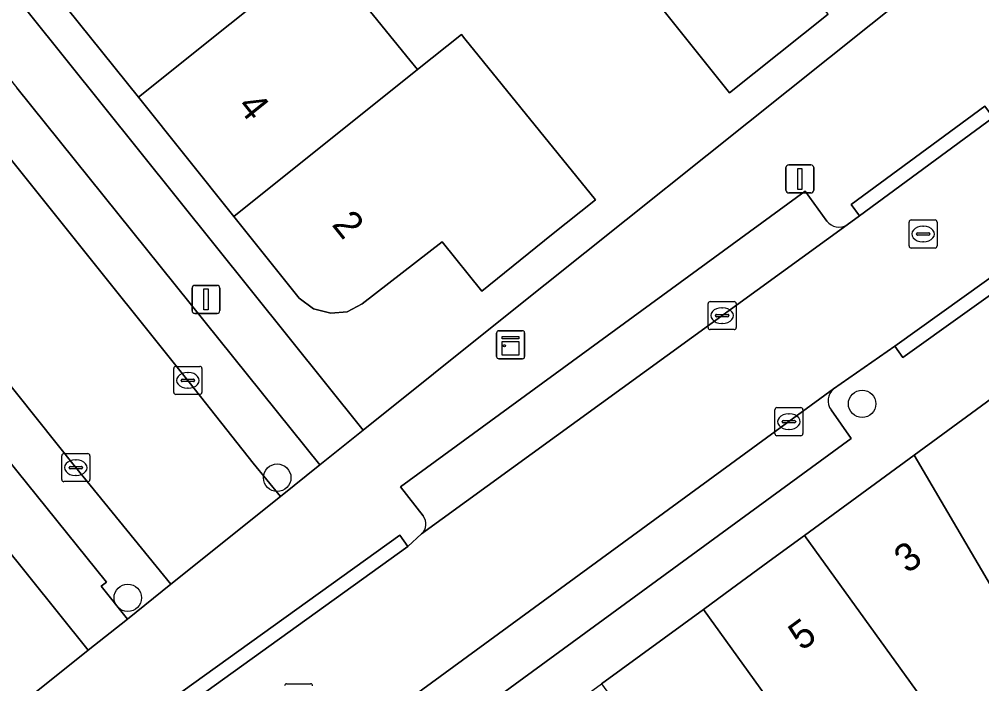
# Model space of a CAD drawing. Extents: x 161771 to 163125, y 382475 to 383179.
# Drawn here: x 162131 to 162165.3, y 382895.24 to 382918.93 of the extents above; entities that cross this region are included whole.
import ezdxf

# ---------------------------------------------------------------- set-up
doc = ezdxf.new("R2010")
doc.units = 0
for name, color, linetype in [('IMGEO_Boom', 7, 'Continuous'), ('IMGEO_Erf', 7, 'Continuous'), ('IMGEO_Kast', 7, 'Continuous'), ('IMGEO_Kolk', 7, 'Continuous'), ('IMGEO_Lichtmast', 7, 'Continuous'), ('IMGEO_Pand', 7, 'Continuous'), ('IMGEO_Pand_nummerreeks', 7, 'Continuous'), ('IMGEO_Parkeervlak_open', 7, 'Continuous'), ('IMGEO_Rijbaan_lokaal_open', 7, 'Continuous'), ('IMGEO_Rioolput', 7, 'Continuous'), ('IMGEO_Voetpad_open', 7, 'Continuous'), ('IMGEO_Woonerf_open', 7, 'Continuous')]:
    doc.layers.add(name, color=color, linetype=linetype)

msp = doc.modelspace()

# ---------------------------------------------------------------- linework, layer by layer
at = {"layer": 'IMGEO_Boom'}
for centre in [(162161.037, 382905.221), (162140.194, 382902.589), (162134.866, 382898.309)]:
    msp.add_circle(centre, 0.489, dxfattribs=at)
at = {"layer": 'IMGEO_Erf'}
for points in [[(162119.361, 382885.166), (162133.454, 382896.443), (162070.869, 382974.514)], [(162096.877, 382962.151), (162143.255, 382904.278), (162148.274, 382908.294), (162171.48, 382926.845)], [(162159.833, 382919.109), (162156.311, 382916.302), (162151.576, 382922.244)], [(162141.765, 382921.364), (162144.924, 382917.47), (162145.193, 382917.138), (162146.755, 382918.388), (162146.88, 382918.233), (162151.533, 382912.494), (162149.969, 382911.248), (162147.491, 382909.238), (162146.068, 382910.992), (162143.222, 382908.782), (162142.685, 382908.505), (162142.11, 382908.456), (162141.488, 382908.607), (162140.975, 382908.991), (162138.647, 382911.901), (162135.247, 382916.15), (162131.831, 382920.419)]]:
    msp.add_lwpolyline(points, dxfattribs=at)
at = {"layer": 'IMGEO_Kast'}
for p, q in [((162148.01, 382906.904), (162148.01, 382907.745)), ((162148.01, 382907.745), (162148.01, 382906.904)), ((162148.085, 382907.829), (162148.926, 382907.829)), ((162148.926, 382907.829), (162148.085, 382907.829)), ((162149.01, 382907.754), (162149.01, 382906.913)), ((162149.01, 382906.913), (162149.01, 382907.754)), ((162148.935, 382906.829), (162148.094, 382906.829)), ((162148.094, 382906.829), (162148.935, 382906.829))]:
    msp.add_line(p, q, dxfattribs=at)
for points in [[(162148.205, 382907.619), (162148.805, 382907.619), (162148.805, 382907.534), (162148.205, 382907.534), (162148.205, 382907.619)], [(162148.205, 382907.444), (162148.805, 382907.444), (162148.805, 382906.955), (162148.205, 382906.955), (162148.205, 382907.444)]]:
    msp.add_lwpolyline(points, dxfattribs=at)
msp.add_circle((162148.289, 382907.293), 0.0377, dxfattribs=at)
for centre, start, end in [((162148.088, 382907.751), 92.4484, 184.2845), ((162148.088, 382907.751), 92.4484, 184.2845), ((162148.932, 382907.751), 2.4484, 94.2845), ((162148.932, 382907.751), 2.4484, 94.2845), ((162148.088, 382906.907), 182.4484, 274.2845), ((162148.088, 382906.907), 182.4484, 274.2845), ((162148.932, 382906.907), 272.4484, 4.2845), ((162148.932, 382906.907), 272.4484, 4.2845)]:
    msp.add_arc(centre, 0.0779, start, end, dxfattribs=at)
at = {"layer": 'IMGEO_Kolk'}
for p, q in [((162155.549, 382907.941), (162155.549, 382908.793)), ((162155.624, 382908.867), (162156.476, 382908.867)), ((162156.037, 382908.647), (162156.062, 382908.647)), ((162156.55, 382908.793), (162156.55, 382907.941)), ((162155.808, 382908.361), (162155.808, 382908.373)), ((162156.246, 382908.324), (162155.848, 382908.324)), ((162155.851, 382908.41), (162156.249, 382908.41)), ((162156.292, 382908.373), (162156.292, 382908.361)), ((162156.06, 382908.087), (162156.035, 382908.087)), ((162156.476, 382907.867), (162155.624, 382907.867)), ((162136.583, 382906.557), (162137.435, 382906.557)), ((162136.508, 382905.631), (162136.508, 382906.483)), ((162136.996, 382906.337), (162137.021, 382906.337)), ((162137.509, 382906.483), (162137.509, 382905.631)), ((162136.767, 382906.051), (162136.767, 382906.063)), ((162137.205, 382906.014), (162136.807, 382906.014)), ((162136.81, 382906.1), (162137.208, 382906.1)), ((162137.251, 382906.063), (162137.251, 382906.051)), ((162137.435, 382905.557), (162136.583, 382905.557)), ((162137.019, 382905.777), (162136.994, 382905.777)), ((162157.927, 382904.16), (162157.927, 382905.012)), ((162158.002, 382905.086), (162158.854, 382905.086)), ((162158.415, 382904.866), (162158.44, 382904.866)), ((162158.928, 382905.012), (162158.928, 382904.16)), ((162158.186, 382904.58), (162158.186, 382904.592)), ((162158.624, 382904.543), (162158.226, 382904.543)), ((162158.229, 382904.629), (162158.627, 382904.629)), ((162158.67, 382904.592), (162158.67, 382904.58)), ((162158.438, 382904.306), (162158.413, 382904.306)), ((162158.854, 382904.086), (162158.002, 382904.086)), ((162132.591, 382903.448), (162133.443, 382903.448)), ((162132.516, 382902.522), (162132.516, 382903.374)), ((162133.004, 382903.228), (162133.029, 382903.228)), ((162133.517, 382903.374), (162133.517, 382902.522)), ((162132.775, 382902.942), (162132.775, 382902.954)), ((162133.213, 382902.905), (162132.815, 382902.905)), ((162132.818, 382902.991), (162133.216, 382902.991)), ((162133.259, 382902.954), (162133.259, 382902.942)), ((162133.443, 382902.448), (162132.591, 382902.448)), ((162133.027, 382902.668), (162133.002, 382902.668))]:
    msp.add_line(p, q, dxfattribs=at)
for points in [[(162155.549, 382907.941), (162155.549, 382908.793)], [(162155.624, 382908.867), (162156.476, 382908.867)], [(162156.55, 382908.793), (162156.55, 382907.941)], [(162156.476, 382907.867), (162155.624, 382907.867)], [(162136.583, 382906.557), (162137.435, 382906.557)], [(162136.508, 382905.631), (162136.508, 382906.483)], [(162137.509, 382906.483), (162137.509, 382905.631)], [(162137.435, 382905.557), (162136.583, 382905.557)], [(162157.927, 382904.16), (162157.927, 382905.012)], [(162158.002, 382905.086), (162158.854, 382905.086)], [(162158.928, 382905.012), (162158.928, 382904.16)], [(162158.854, 382904.086), (162158.002, 382904.086)], [(162132.591, 382903.448), (162133.443, 382903.448)], [(162132.516, 382902.522), (162132.516, 382903.374)], [(162133.517, 382903.374), (162133.517, 382902.522)], [(162133.443, 382902.448), (162132.591, 382902.448)]]:
    msp.add_lwpolyline(points, dxfattribs=at)
for centre, radius, start, end in [((162155.626, 382908.791), 0.0765, 91.552, 178.448), ((162155.626, 382908.791), 0.0765, 91.552, 178.448), ((162156.474, 382908.791), 0.0765, 1.552, 88.448), ((162156.474, 382908.791), 0.0765, 1.552, 88.448), ((162155.848, 382908.37), 0.0403, 85.8775, 175.7526), ((162155.845, 382908.36), 0.0366, 178.938, 274.7102), ((162156.249, 382908.367), 0.043, 264.8664, 352.4533), ((162156.253, 382908.372), 0.0386, 1.7309, 96.639), ((162155.626, 382907.943), 0.0765, 181.552, 268.448), ((162155.626, 382907.943), 0.0765, 181.552, 268.448), ((162156.474, 382907.943), 0.0765, 271.552, 358.448), ((162156.474, 382907.943), 0.0765, 271.552, 358.448), ((162136.585, 382906.481), 0.0765, 91.552, 178.448), ((162136.585, 382906.481), 0.0765, 91.552, 178.448), ((162137.433, 382906.481), 0.0765, 1.552, 88.448), ((162137.433, 382906.481), 0.0765, 1.552, 88.448), ((162136.807, 382906.06), 0.0403, 85.8775, 175.7526), ((162136.804, 382906.05), 0.0366, 178.938, 274.7102), ((162137.208, 382906.057), 0.043, 264.8664, 352.4533), ((162137.212, 382906.062), 0.0386, 1.7309, 96.639), ((162136.585, 382905.633), 0.0765, 181.552, 268.448), ((162136.585, 382905.633), 0.0765, 181.552, 268.448), ((162137.433, 382905.633), 0.0765, 271.552, 358.448), ((162137.433, 382905.633), 0.0765, 271.552, 358.448), ((162158.004, 382905.01), 0.0765, 91.552, 178.448), ((162158.004, 382905.01), 0.0765, 91.552, 178.448), ((162158.852, 382905.01), 0.0765, 1.552, 88.448), ((162158.852, 382905.01), 0.0765, 1.552, 88.448), ((162158.226, 382904.589), 0.0403, 85.8775, 175.7526), ((162158.223, 382904.579), 0.0366, 178.938, 274.7102), ((162158.627, 382904.586), 0.043, 264.8664, 352.4533), ((162158.631, 382904.591), 0.0386, 1.7309, 96.639), ((162158.004, 382904.162), 0.0765, 181.552, 268.448), ((162158.004, 382904.162), 0.0765, 181.552, 268.448), ((162158.852, 382904.162), 0.0765, 271.552, 358.448), ((162158.852, 382904.162), 0.0765, 271.552, 358.448), ((162132.593, 382903.372), 0.0765, 91.552, 178.448), ((162132.593, 382903.372), 0.0765, 91.552, 178.448), ((162133.441, 382903.372), 0.0765, 1.552, 88.448), ((162133.441, 382903.372), 0.0765, 1.552, 88.448), ((162132.815, 382902.951), 0.0403, 85.8775, 175.7526), ((162132.812, 382902.941), 0.0366, 178.938, 274.7102), ((162133.216, 382902.948), 0.043, 264.8664, 352.4533), ((162133.22, 382902.953), 0.0386, 1.7309, 96.639), ((162132.593, 382902.524), 0.0765, 181.552, 268.448), ((162132.593, 382902.524), 0.0765, 181.552, 268.448), ((162133.441, 382902.524), 0.0765, 271.552, 358.448), ((162133.441, 382902.524), 0.0765, 271.552, 358.448)]:
    msp.add_arc(centre, radius, start, end, dxfattribs=at)
for centre, major_axis, ratio, start_param, end_param in [((162156.036, 382908.367), (-0.387, 0.002), 0.722429, 4.712389, 7.853982), ((162156.061, 382908.367), (-0.39, 0.002), 0.717154, 1.570796, 4.712389), ((162136.995, 382906.057), (-0.387, 0.002), 0.722429, 4.712389, 7.853982), ((162137.02, 382906.057), (-0.39, 0.002), 0.717154, 1.570796, 4.712389), ((162158.414, 382904.586), (-0.387, 0.002), 0.722429, 4.712389, 7.853982), ((162158.439, 382904.586), (-0.39, 0.002), 0.717154, 1.570796, 4.712389), ((162133.003, 382902.948), (-0.387, 0.002), 0.722429, 4.712389, 7.853982), ((162133.028, 382902.948), (-0.39, 0.002), 0.717154, 1.570796, 4.712389)]:
    msp.add_ellipse(centre, major_axis=major_axis, ratio=ratio, start_param=start_param, end_param=end_param, dxfattribs=at)
at = {"layer": 'IMGEO_Lichtmast'}
for p, q in [((162158.424, 382913.74), (162159.214, 382913.74)), ((162159.214, 382913.74), (162158.424, 382913.74)), ((162158.324, 382912.84), (162158.324, 382913.64)), ((162158.324, 382913.64), (162158.324, 382912.84)), ((162159.314, 382913.64), (162159.314, 382912.84)), ((162159.314, 382912.84), (162159.314, 382913.64)), ((162159.214, 382912.74), (162158.424, 382912.74)), ((162158.424, 382912.74), (162159.214, 382912.74)), ((162137.16, 382908.543), (162137.16, 382909.343)), ((162137.16, 382909.343), (162137.16, 382908.543)), ((162137.26, 382909.443), (162138.05, 382909.443)), ((162138.05, 382909.443), (162137.26, 382909.443)), ((162138.15, 382909.343), (162138.15, 382908.543)), ((162138.15, 382908.543), (162138.15, 382909.343)), ((162138.05, 382908.443), (162137.26, 382908.443)), ((162137.26, 382908.443), (162138.05, 382908.443))]:
    msp.add_line(p, q, dxfattribs=at)
for points in [[(162158.744, 382913.615), (162158.894, 382913.615), (162158.894, 382912.865), (162158.744, 382912.865), (162158.744, 382913.615)], [(162137.58, 382909.318), (162137.73, 382909.318), (162137.73, 382908.568), (162137.58, 382908.568), (162137.58, 382909.318)]]:
    msp.add_lwpolyline(points, dxfattribs=at)
for centre, start, end in [((162158.424, 382913.64), 90, 180), ((162158.424, 382913.64), 90, 180), ((162159.214, 382913.64), 0, 90), ((162159.214, 382913.64), 360, 90), ((162158.424, 382912.84), 180, 270), ((162158.424, 382912.84), 180, 270), ((162159.214, 382912.84), 270, 0), ((162159.214, 382912.84), 270, 0), ((162137.26, 382909.343), 90, 180), ((162137.26, 382909.343), 90, 180), ((162138.05, 382909.343), 0, 90), ((162138.05, 382909.343), 360, 90), ((162137.26, 382908.543), 180, 270), ((162137.26, 382908.543), 180, 270), ((162138.05, 382908.543), 270, 0), ((162138.05, 382908.543), 270, 0)]:
    msp.add_arc(centre, 0.1, start, end, dxfattribs=at)
at = {"layer": 'IMGEO_Pand'}
for points in [[(162131.831, 382920.419), (162135.247, 382916.15), (162141.765, 382921.364), (162144.342, 382923.425), (162142.792, 382925.336), (162140.23, 382923.256), (162138.32, 382925.611)], [(162155.07, 382925.04), (162152.267, 382922.797), (162151.576, 382922.244), (162156.311, 382916.302), (162159.833, 382919.109)], [(162145.193, 382917.138), (162144.924, 382917.47), (162141.765, 382921.364), (162135.247, 382916.15), (162138.647, 382911.901)], [(162151.533, 382912.494), (162146.88, 382918.233), (162146.755, 382918.388), (162145.193, 382917.138), (162138.647, 382911.901), (162140.975, 382908.991), (162141.488, 382908.607), (162142.11, 382908.456), (162142.685, 382908.505), (162143.222, 382908.782), (162146.068, 382910.992), (162147.491, 382909.238), (162149.969, 382911.248)], [(162162.894, 382903.388), (162158.981, 382900.527), (162166.903, 382889.54), (162168.819, 382890.922), (162168.751, 382891.017), (162165.619, 382895.402), (162166.964, 382896.454), (162165.055, 382899.707)], [(162158.981, 382900.527), (162157.86, 382899.707), (162156.384, 382898.628), (162155.381, 382897.894), (162160.22, 382891.181), (162162.032, 382892.502), (162165.124, 382888.257), (162166.903, 382889.54)], [(162155.381, 382897.894), (162151.754, 382895.242), (162159.699, 382884.336), (162161.333, 382885.487), (162162.558, 382886.35), (162160.945, 382888.641), (162159.719, 382887.778), (162158.305, 382889.786), (162160.22, 382891.181)]]:
    msp.add_lwpolyline(points, close=True, dxfattribs=at)
at = {"layer": 'IMGEO_Parkeervlak_open'}
for points in [[(162093.61, 382961.455), (162093.815, 382962.38), (162093.77, 382962.818), (162093.596, 382963.187), (162079.124, 382981.195), (162077.729, 382980.054), (162078.737, 382978.916), (162082.043, 382974.428), (162092.505, 382961.71), (162095.538, 382957.905), (162096.482, 382956.694), (162109.857, 382939.975), (162119.562, 382927.825), (162122.601, 382924.093), (162122.694, 382923.973), (162123.703, 382922.674), (162137.054, 382905.998), (162139.34, 382903.102), (162140.307, 382901.917), (162141.717, 382903.048), (162130.917, 382916.483)], [(162124.165, 382911.199), (162134.109, 382898.871), (162133.924, 382898.728), (162134.86, 382897.546), (162136.406, 382898.79), (162133.002, 382902.97), (162119.914, 382919.373), (162118.699, 382920.849), (162115.63, 382924.69), (162105.843, 382937.034), (162092.723, 382953.402), (162091.583, 382954.731), (162088.546, 382958.539), (162073.842, 382976.876), (162072.439, 382975.73), (162086.885, 382957.787)], [(162159.785, 382911.734), (162159.007, 382912.797), (162144.588, 382902.261), (162145.397, 382901.226)], [(162145.341, 382900.591), (162160.501, 382911.597)], [(162160.018, 382905.751), (162137.732, 382889.454), (162135.365, 382887.723), (162125.393, 382880.431)], [(162126.151, 382880.323), (162126.857, 382879.291), (162140.141, 382888.996), (162160.652, 382903.982), (162159.93, 382905.004)]]:
    msp.add_lwpolyline(points, dxfattribs=at)
for centre, radius, start, end in [((162160.218, 382912.059), 0.542, 216.8935, 301.4423), ((162160.382, 382905.329), 0.557, 130.8339, 215.7286), ((162145.032, 382900.938), 0.465, 311.6582, 38.2622)]:
    msp.add_arc(centre, radius, start, end, dxfattribs=at)
at = {"layer": 'IMGEO_Rijbaan_lokaal_open'}
for points in [[(162136.672, 382894.252), (162135.907, 382893.712), (162135.462, 382893.398), (162135.086, 382893.123), (162137.732, 382889.454), (162160.018, 382905.751), (162162.202, 382907.274), (162168.658, 382911.904), (162169.91, 382912.836), (162202.304, 382936.515), (162199.544, 382940.182), (162198.547, 382939.458), (162197.661, 382938.791), (162196.496, 382937.909), (162189.901, 382933.103), (162188.634, 382932.194), (162166.246, 382915.883), (162165.705, 382915.432), (162160.94, 382911.921), (162160.501, 382911.597), (162145.341, 382900.591), (162144.852, 382900.14)], [(162122.694, 382923.973), (162118.699, 382920.849), (162119.914, 382919.373), (162133.002, 382902.97), (162136.406, 382898.79), (162140.307, 382901.917), (162139.34, 382903.102), (162137.054, 382905.998), (162123.703, 382922.674)]]:
    msp.add_lwpolyline(points, close=True, dxfattribs=at)
at = {"layer": 'IMGEO_Rioolput'}
for p, q in [((162162.711, 382910.85), (162162.711, 382911.702)), ((162162.786, 382911.776), (162163.638, 382911.776)), ((162163.712, 382911.702), (162163.712, 382910.85)), ((162163.013, 382911.319), (162163.411, 382911.319)), ((162163.199, 382911.556), (162163.224, 382911.556)), ((162162.97, 382911.27), (162162.97, 382911.282)), ((162163.408, 382911.233), (162163.01, 382911.233)), ((162163.222, 382910.996), (162163.197, 382910.996)), ((162163.454, 382911.282), (162163.454, 382911.27)), ((162163.638, 382910.776), (162162.786, 382910.776)), ((162140.53, 382895.244), (162141.382, 382895.244))]:
    msp.add_line(p, q, dxfattribs=at)
for points in [[(162162.711, 382910.85), (162162.711, 382911.702)], [(162162.786, 382911.776), (162163.638, 382911.776)], [(162163.712, 382911.702), (162163.712, 382910.85)], [(162163.638, 382910.776), (162162.786, 382910.776)], [(162140.53, 382895.244), (162141.382, 382895.244)]]:
    msp.add_lwpolyline(points, dxfattribs=at)
for centre, radius, start, end in [((162162.788, 382911.7), 0.0765, 91.552, 178.448), ((162162.788, 382911.7), 0.0765, 91.552, 178.448), ((162163.636, 382911.7), 0.0765, 1.552, 88.448), ((162163.636, 382911.7), 0.0765, 1.552, 88.448), ((162163.01, 382911.279), 0.0403, 85.8775, 175.7526), ((162163.415, 382911.281), 0.0386, 1.7309, 96.639), ((162163.007, 382911.269), 0.0366, 178.938, 274.7102), ((162163.411, 382911.276), 0.043, 264.8664, 352.4533), ((162162.788, 382910.852), 0.0765, 181.552, 268.448), ((162162.788, 382910.852), 0.0765, 181.552, 268.448), ((162163.636, 382910.852), 0.0765, 271.552, 358.448), ((162163.636, 382910.852), 0.0765, 271.552, 358.448), ((162140.532, 382895.168), 0.0765, 91.552, 178.448), ((162140.532, 382895.168), 0.0765, 91.552, 178.448), ((162141.38, 382895.168), 0.0765, 1.552, 88.448), ((162141.38, 382895.168), 0.0765, 1.552, 88.448)]:
    msp.add_arc(centre, radius, start, end, dxfattribs=at)
for centre, major_axis, ratio, start_param, end_param in [((162163.198, 382911.276), (-0.387, 0.002), 0.722429, 4.712389, 7.853982), ((162163.223, 382911.276), (-0.39, 0.002), 0.717154, 1.570796, 4.712389)]:
    msp.add_ellipse(centre, major_axis=major_axis, ratio=ratio, start_param=start_param, end_param=end_param, dxfattribs=at)
at = {"layer": 'IMGEO_Voetpad_open'}
for points in [[(162096.877, 382962.151), (162095.925, 382963.339), (162080.629, 382982.426), (162079.124, 382981.195), (162093.596, 382963.187), (162097.145, 382958.713), (162100.29, 382954.805), (162103.84, 382950.349), (162106.975, 382946.425), (162110.564, 382941.959), (162113.949, 382937.714), (162117.4, 382933.368), (162120.641, 382929.343), (162124.209, 382924.889), (162127.356, 382920.977), (162130.917, 382916.483), (162141.717, 382903.048), (162143.255, 382904.278)], [(162133.924, 382898.728), (162134.109, 382898.871), (162124.165, 382911.199), (162120.69, 382915.541), (162117.481, 382919.612), (162113.979, 382923.976), (162110.861, 382927.877), (162107.319, 382932.31), (162103.886, 382936.605), (162100.316, 382941.041), (162097.168, 382944.986), (162093.588, 382949.417), (162090.481, 382953.329), (162086.885, 382957.787), (162072.439, 382975.73), (162070.869, 382974.514), (162133.454, 382896.443), (162134.86, 382897.546)], [(162165.705, 382915.432), (162165.409, 382915.834), (162160.644, 382912.323), (162160.94, 382911.921)], [(162168.658, 382911.904), (162162.202, 382907.274), (162162.493, 382906.868), (162168.949, 382911.498)], [(162136.672, 382894.252), (162144.852, 382900.14), (162144.56, 382900.545), (162136.38, 382894.657)]]:
    msp.add_lwpolyline(points, close=True, dxfattribs=at)
for points in [[(162171.48, 382926.845), (162148.274, 382908.294), (162143.255, 382904.278), (162141.717, 382903.048), (162140.307, 382901.917), (162136.406, 382898.79), (162134.86, 382897.546), (162133.454, 382896.443), (162119.361, 382885.166), (162098.181, 382868.21), (162098.069, 382868.327), (162097.563, 382867.829), (162093.939, 382864.262), (162094.574, 382863.381), (162091.459, 382860.295), (162087.763, 382856.634), (162084.218, 382853.122), (162080.644, 382849.582), (162076.859, 382845.833), (162073.253, 382842.261), (162069.123, 382838.17), (162066.249, 382835.323), (162065.602, 382834.655), (162062.458, 382831.409)], [(162160.501, 382911.597), (162160.94, 382911.921), (162160.644, 382912.323), (162165.409, 382915.834), (162165.705, 382915.432), (162166.246, 382915.883)], [(162145.397, 382901.226), (162144.588, 382902.261), (162159.007, 382912.797), (162159.785, 382911.734)], [(162169.91, 382912.836), (162168.658, 382911.904), (162168.949, 382911.498), (162162.493, 382906.868), (162162.202, 382907.274), (162160.018, 382905.751)], [(162130.04, 382879.365), (162133.731, 382882.064), (162137.303, 382884.676), (162140.946, 382887.34), (162141.358, 382887.641), (162144.533, 382889.962), (162148.144, 382892.603), (162151.754, 382895.242), (162155.381, 382897.894), (162156.384, 382898.628), (162157.86, 382899.707), (162158.981, 382900.527), (162162.894, 382903.388), (162170.933, 382909.288)], [(162159.93, 382905.004), (162160.652, 382903.982), (162140.141, 382888.996), (162126.857, 382879.291), (162126.151, 382880.323)], [(162135.462, 382893.398), (162135.907, 382893.712), (162136.672, 382894.252), (162136.38, 382894.657), (162144.56, 382900.545), (162144.852, 382900.14), (162145.341, 382900.591)]]:
    msp.add_lwpolyline(points, dxfattribs=at)
for centre, radius, start, end in [((162160.218, 382912.059), 0.542, 216.8935, 301.4423), ((162160.382, 382905.329), 0.557, 130.8339, 215.7286), ((162145.032, 382900.938), 0.465, 311.6582, 38.2622)]:
    msp.add_arc(centre, radius, start, end, dxfattribs=at)
at = {"layer": 'IMGEO_Woonerf_open'}
msp.add_lwpolyline([(162170.933, 382909.288), (162162.894, 382903.388), (162165.055, 382899.707), (162166.964, 382896.454)], dxfattribs=at)

# ---------------------------------------------------------------- texts
at = {"layer": 'IMGEO_Pand_nummerreeks'}
for s, rotation, p in [('4', 308.663, (162138.74, 382915.816)), ('2', 308.663, (162142.112, 382911.603)), ('3', 36.1708, (162162.651, 382899.147)), ('5', 36.1766, (162158.886, 382896.394))]:
    msp.add_text(s, height=1, rotation=rotation, dxfattribs=at).set_placement(p)

doc.saveas('drawing.dxf')
